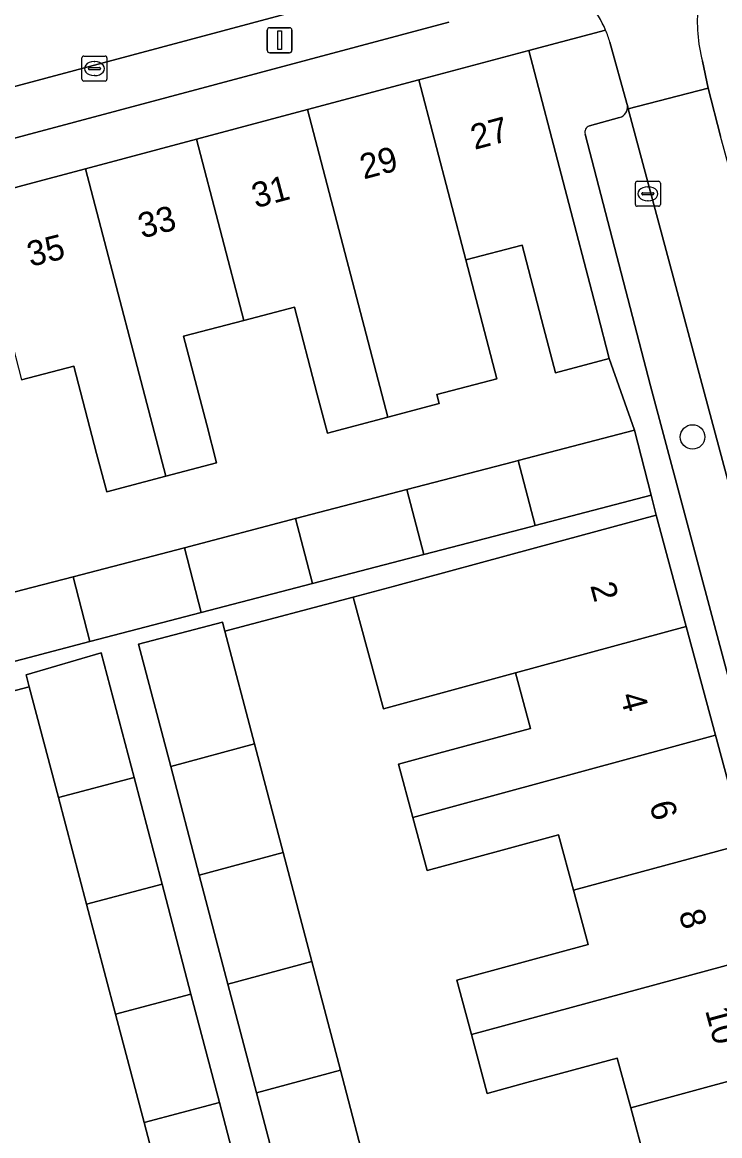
# Model space of a CAD drawing. Extents: x 162542 to 163147, y 380779 to 381521.
# Drawn here: x 162999.98 to 163027.86, y 381074.17 to 381118.69 of the extents above; entities that cross this region are included whole.
import ezdxf

# ---------------------------------------------------------------- set-up
doc = ezdxf.new("R2010")
doc.units = 0
for name, color, linetype in [('IMGEO_Boom', 7, 'Continuous'), ('IMGEO_Erf', 7, 'Continuous'), ('IMGEO_Kolk', 7, 'Continuous'), ('IMGEO_Lichtmast', 7, 'Continuous'), ('IMGEO_Muur', 7, 'Continuous'), ('IMGEO_Pand', 7, 'Continuous'), ('IMGEO_Pand_nummerreeks', 7, 'Continuous'), ('IMGEO_Parkeervlak_open', 7, 'Continuous'), ('IMGEO_Rijbaan_lokaal_open', 7, 'Continuous'), ('IMGEO_Voetpad_open', 7, 'Continuous')]:
    doc.layers.add(name, color=color, linetype=linetype)

msp = doc.modelspace()

# ---------------------------------------------------------------- linework, layer by layer
at = {"layer": 'IMGEO_Boom'}
msp.add_circle((163026.776, 381102.113), 0.489, dxfattribs=at)
at = {"layer": 'IMGEO_Erf'}
for points in [[(162997.557, 381095.362), (163000, 381096), (163002.005, 381096.523), (163006.456, 381097.685), (163010.904, 381098.845), (163015.354, 381100.007), (163019.613, 381101.118), (163019.804, 381101.168), (163024.451, 381102.38), (163023.444, 381105.243), (163021.293, 381104.681), (163020.819, 381106.496), (163019.962, 381109.779), (163017.709, 381109.191), (163018.95, 381104.439), (163016.548, 381103.812), (163016.644, 381103.445), (163014.598, 381102.901), (163012.174, 381102.257), (163011.754, 381103.865), (163010.857, 381107.3), (163008.835, 381106.772), (163006.424, 381106.143), (163007.349, 381102.598), (163007.745, 381101.079), (163005.711, 381100.538), (163003.351, 381099.911), (163002.95, 381101.449), (163002.039, 381104.94), (162999.951, 381104.395)], [(163024.887, 381073.152), (163024.307, 381075.287), (163023.765, 381077.281), (163020.157, 381076.301), (163018.568, 381075.869), (163017.934, 381078.218), (163017.348, 381080.39), (163018.93, 381080.82), (163022.606, 381081.819), (163022.017, 381083.987), (163021.414, 381086.203), (163017.787, 381085.217), (163016.163, 381084.776), (163015.589, 381086.903), (163015.016, 381089.024), (163016.633, 381089.464), (163020.296, 381090.46), (163019.694, 381092.678), (163014.417, 381091.246), (163013.213, 381095.702), (163008.079, 381094.353), (163009.264, 381089.846), (163010.407, 381085.496), (163011.551, 381081.145), (163012.694, 381076.795), (163013.837, 381072.445)], [(163005.987, 381070.367), (163004.846, 381074.7), (163003.704, 381079.036), (163002.549, 381083.426), (163001.425, 381087.692), (163000.258, 381092.125), (162993.238, 381090.278), (162993.844, 381087.979), (162991.901, 381087.466), (162988.211, 381086.491), (162988.779, 381084.344), (162992.497, 381085.326), (162993.101, 381083.041), (162995.014, 381083.547), (162996.389, 381083.91), (162996.918, 381081.91), (162997.485, 381079.764), (162994.218, 381078.9), (162994.806, 381076.675), (162992.491, 381076.063), (162993.072, 381073.867), (162996.808, 381074.855), (162998.633, 381075.337), (162999.186, 381073.201)]]:
    msp.add_lwpolyline(points, dxfattribs=at)
at = {"layer": 'IMGEO_Kolk'}
for p, q in [((163002.362, 381116.413), (163002.362, 381117.265)), ((163002.437, 381117.339), (163003.289, 381117.339)), ((163002.85, 381117.119), (163002.875, 381117.119)), ((163003.363, 381117.265), (163003.363, 381116.413)), ((163002.621, 381116.833), (163002.621, 381116.845)), ((163003.059, 381116.796), (163002.661, 381116.796)), ((163002.664, 381116.882), (163003.062, 381116.882)), ((163002.873, 381116.559), (163002.848, 381116.559)), ((163003.105, 381116.845), (163003.105, 381116.833)), ((163003.289, 381116.339), (163002.437, 381116.339)), ((163024.492, 381111.407), (163024.492, 381112.259)), ((163024.567, 381112.333), (163025.419, 381112.333)), ((163024.98, 381112.113), (163025.005, 381112.113)), ((163025.493, 381112.259), (163025.493, 381111.407)), ((163024.751, 381111.827), (163024.751, 381111.839)), ((163025.189, 381111.79), (163024.791, 381111.79)), ((163024.794, 381111.876), (163025.192, 381111.876)), ((163025.235, 381111.839), (163025.235, 381111.827)), ((163025.419, 381111.333), (163024.567, 381111.333)), ((163025.003, 381111.553), (163024.978, 381111.553))]:
    msp.add_line(p, q, dxfattribs=at)
for points in [[(163002.362, 381116.413), (163002.362, 381117.265)], [(163002.437, 381117.339), (163003.289, 381117.339)], [(163003.363, 381117.265), (163003.363, 381116.413)], [(163003.289, 381116.339), (163002.437, 381116.339)], [(163024.492, 381111.407), (163024.492, 381112.259)], [(163024.567, 381112.333), (163025.419, 381112.333)], [(163025.493, 381112.259), (163025.493, 381111.407)], [(163025.419, 381111.333), (163024.567, 381111.333)]]:
    msp.add_lwpolyline(points, dxfattribs=at)
for centre, radius, start, end in [((163002.439, 381117.263), 0.0765, 91.552, 178.448), ((163002.439, 381117.263), 0.0765, 91.552, 178.448), ((163003.287, 381117.263), 0.0765, 1.552, 88.448), ((163003.287, 381117.263), 0.0765, 1.552, 88.448), ((163002.661, 381116.842), 0.0403, 85.8775, 175.7526), ((163002.658, 381116.832), 0.0366, 178.938, 274.7102), ((163003.062, 381116.839), 0.043, 264.8664, 352.4533), ((163003.066, 381116.844), 0.0386, 1.7309, 96.639), ((163002.439, 381116.415), 0.0765, 181.552, 268.448), ((163002.439, 381116.415), 0.0765, 181.552, 268.448), ((163003.287, 381116.415), 0.0765, 271.552, 358.448), ((163003.287, 381116.415), 0.0765, 271.552, 358.448), ((163024.569, 381112.257), 0.0765, 91.552, 178.448), ((163024.569, 381112.257), 0.0765, 91.552, 178.448), ((163025.417, 381112.257), 0.0765, 1.552, 88.448), ((163025.417, 381112.257), 0.0765, 1.552, 88.448), ((163024.791, 381111.836), 0.0403, 85.8775, 175.7526), ((163024.788, 381111.826), 0.0366, 178.938, 274.7102), ((163025.192, 381111.833), 0.043, 264.8664, 352.4533), ((163025.196, 381111.838), 0.0386, 1.7309, 96.639), ((163024.569, 381111.409), 0.0765, 181.552, 268.448), ((163024.569, 381111.409), 0.0765, 181.552, 268.448), ((163025.417, 381111.409), 0.0765, 271.552, 358.448), ((163025.417, 381111.409), 0.0765, 271.552, 358.448)]:
    msp.add_arc(centre, radius, start, end, dxfattribs=at)
for centre, major_axis, ratio, start_param, end_param in [((163002.849, 381116.839), (-0.387, 0.002), 0.722429, 4.712389, 7.853982), ((163002.874, 381116.839), (-0.39, 0.002), 0.717154, 1.570796, 4.712389), ((163024.979, 381111.833), (-0.387, 0.002), 0.722429, 4.712389, 7.853982), ((163025.004, 381111.833), (-0.39, 0.002), 0.717154, 1.570796, 4.712389)]:
    msp.add_ellipse(centre, major_axis=major_axis, ratio=ratio, start_param=start_param, end_param=end_param, dxfattribs=at)
at = {"layer": 'IMGEO_Lichtmast'}
for p, q in [((163009.77, 381117.571), (163009.77, 381118.371)), ((163009.77, 381118.371), (163009.77, 381117.571)), ((163009.87, 381118.471), (163010.66, 381118.471)), ((163010.66, 381118.471), (163009.87, 381118.471)), ((163010.76, 381118.371), (163010.76, 381117.571)), ((163010.76, 381117.571), (163010.76, 381118.371)), ((163010.66, 381117.471), (163009.87, 381117.471)), ((163009.87, 381117.471), (163010.66, 381117.471))]:
    msp.add_line(p, q, dxfattribs=at)
msp.add_lwpolyline([(163010.19, 381118.346), (163010.34, 381118.346), (163010.34, 381117.596), (163010.19, 381117.596), (163010.19, 381118.346)], dxfattribs=at)
for centre, start, end in [((163009.87, 381118.371), 90, 180), ((163009.87, 381118.371), 90, 180), ((163010.66, 381118.371), 0, 90), ((163010.66, 381118.371), 360, 90), ((163009.87, 381117.571), 180, 270), ((163009.87, 381117.571), 180, 270), ((163010.66, 381117.571), 270, 0), ((163010.66, 381117.571), 270, 0)]:
    msp.add_arc(centre, 0.1, start, end, dxfattribs=at)
at = {"layer": 'IMGEO_Muur'}
msp.add_lwpolyline([(163023.444, 381105.243), (163024.451, 381102.38)], dxfattribs=at)
at = {"layer": 'IMGEO_Pand'}
for points in [[(163017.709, 381109.191), (163019.962, 381109.779), (163020.819, 381106.496), (163021.293, 381104.681), (163023.444, 381105.243), (163022.97, 381107.057), (163020.229, 381117.56), (163015.83, 381116.387)], [(163011.387, 381115.201), (163014.598, 381102.901), (163016.644, 381103.445), (163016.548, 381103.812), (163018.95, 381104.439), (163017.709, 381109.191), (163015.83, 381116.387)], [(163006.944, 381114.016), (163008.835, 381106.772), (163010.857, 381107.3), (163011.754, 381103.865), (163012.174, 381102.257), (163014.598, 381102.901), (163011.387, 381115.201)], [(163005.711, 381100.538), (163007.745, 381101.079), (163007.349, 381102.598), (163006.424, 381106.143), (163008.835, 381106.772), (163006.944, 381114.016), (163002.501, 381112.831)], [(163005.711, 381100.538), (163002.501, 381112.831), (163000, 381112.164), (162998.059, 381111.646), (162999.951, 381104.395), (163002.039, 381104.94), (163002.95, 381101.449), (163003.351, 381099.911)], [(163020.481, 381098.574), (163025.128, 381099.786), (163024.451, 381102.38), (163019.804, 381101.168)], [(163020.481, 381098.574), (163019.804, 381101.168), (163019.613, 381101.118), (163015.354, 381100.007), (163016.031, 381097.412), (163020.291, 381098.524)], [(163011.581, 381096.251), (163016.031, 381097.412), (163015.354, 381100.007), (163010.904, 381098.845)], [(163006.456, 381097.685), (163007.133, 381095.091), (163011.581, 381096.251), (163010.904, 381098.845)], [(163026.522, 381094.532), (163025.317, 381098.99), (163020.492, 381097.679), (163014.81, 381096.136), (163013.213, 381095.702), (163014.417, 381091.246), (163019.694, 381092.678)], [(163002.005, 381096.523), (163002.682, 381093.929), (163007.133, 381095.091), (163006.456, 381097.685)], [(163002.005, 381096.523), (163000, 381096), (162997.557, 381095.362), (162998.235, 381092.768), (163000, 381093.229), (163002.682, 381093.929)], [(163008.079, 381094.353), (163007.986, 381094.708), (163004.625, 381093.826), (163005.911, 381088.935), (163009.264, 381089.846)], [(163026.522, 381094.532), (163019.694, 381092.678), (163020.296, 381090.46), (163016.633, 381089.464), (163015.016, 381089.024), (163015.589, 381086.903), (163027.696, 381090.19)], [(163003.134, 381093.483), (163000.134, 381092.598), (163000.258, 381092.125), (163001.425, 381087.692), (163004.446, 381088.492)], [(163010.407, 381085.496), (163009.264, 381089.846), (163005.911, 381088.935), (163007.054, 381084.586)], [(163027.696, 381090.19), (163015.589, 381086.903), (163016.163, 381084.776), (163017.787, 381085.217), (163021.414, 381086.203), (163022.017, 381083.987), (163028.87, 381085.848)], [(163001.425, 381087.692), (163002.549, 381083.426), (163005.564, 381084.235), (163004.446, 381088.492)], [(163017.934, 381078.218), (163030.044, 381081.506), (163028.87, 381085.848), (163022.017, 381083.987), (163022.606, 381081.819), (163018.93, 381080.82), (163017.348, 381080.39)], [(163010.407, 381085.496), (163007.054, 381084.586), (163008.197, 381080.234), (163011.551, 381081.145)], [(163005.564, 381084.235), (163002.549, 381083.426), (163003.704, 381079.036), (163006.721, 381079.835)], [(163017.934, 381078.218), (163018.568, 381075.869), (163020.157, 381076.301), (163023.765, 381077.281), (163024.307, 381075.287), (163031.218, 381077.163), (163030.044, 381081.506)], [(163009.34, 381075.885), (163012.694, 381076.795), (163011.551, 381081.145), (163008.197, 381080.234)], [(163004.846, 381074.7), (163007.86, 381075.498), (163006.721, 381079.835), (163003.704, 381079.036)], [(163031.218, 381077.163), (163024.307, 381075.287), (163024.887, 381073.152), (163021.3, 381072.178), (163019.683, 381071.739), (163019.329, 381071.643), (163019.925, 381069.436), (163032.392, 381072.821)], [(163009.34, 381075.885), (163010.483, 381071.535), (163013.837, 381072.445), (163012.694, 381076.795)], [(163004.846, 381074.7), (163005.987, 381070.367), (163008.999, 381071.164), (163007.86, 381075.498)]]:
    msp.add_lwpolyline(points, close=True, dxfattribs=at)
at = {"layer": 'IMGEO_Parkeervlak_open'}
for points in [[(163017.219, 381120.83), (163017.107, 381120.8), (163016.022, 381120.51), (162980.068, 381110.891)], [(162981.246, 381109.144), (163017.038, 381118.691)], [(163028.907, 381097.696), (163024.207, 381115.224), (163024.17, 381115.363)], [(163023.86, 381114.888), (163022.656, 381114.552)], [(163022.488, 381114.212), (163025.098, 381104.154), (163040.537, 381046.316), (163041.163, 381044.025)]]:
    msp.add_lwpolyline(points, dxfattribs=at)
for centre, radius, start, end in [((163023.759, 381115.292), 0.417, 284, 9.7406), ((163022.742, 381114.298), 0.268, 108.711, 198.6994)]:
    msp.add_arc(centre, radius, start, end, dxfattribs=at)
at = {"layer": 'IMGEO_Rijbaan_lokaal_open'}
for points in [[(163017.107, 381120.8), (163016.087, 381124.68), (162980.601, 381115.195), (162980.082, 381115.076), (162975.55, 381113.864), (162976.575, 381109.968), (162980.068, 381110.891), (163016.022, 381120.51)], [(163027.891, 381114.14), (163027.397, 381116.055), (163024.207, 381115.224), (163028.907, 381097.696), (163034.368, 381077.25), (163037.584, 381078.128), (163030.851, 381103.35)]]:
    msp.add_lwpolyline(points, close=True, dxfattribs=at)
msp.add_lwpolyline([(163023.47, 381117.898), (163024.15, 381115.438), (163024.17, 381115.363), (163024.207, 381115.224), (163027.397, 381116.055), (163027.173, 381117.133)], dxfattribs=at)
for centre, radius, start, end in [((163019.41, 381116.732), 4.224, 22.9321, 56.5349), ((163033.071, 381118.715), 6.106, 173.9148, 195.0124), ((163019.184, 381116.65), 4.464, 16.2331, 22.7718)]:
    msp.add_arc(centre, radius, start, end, dxfattribs=at)
at = {"layer": 'IMGEO_Voetpad_open'}
for points in [[(163017.038, 381118.691), (162981.246, 381109.144)], [(163000, 381112.164), (163002.501, 381112.831), (163006.944, 381114.016), (163011.387, 381115.201), (163015.83, 381116.387), (163020.229, 381117.56), (163023.3, 381118.378)], [(163023.3, 381118.378), (163020.229, 381117.56), (163022.97, 381107.057), (163023.444, 381105.243), (163024.451, 381102.38), (163025.128, 381099.786), (163025.317, 381098.99), (163026.522, 381094.532), (163027.696, 381090.19), (163028.87, 381085.848), (163030.044, 381081.506), (163031.218, 381077.163), (163032.392, 381072.821), (163033.566, 381068.479), (163034.74, 381064.136), (163035.913, 381059.794), (163037.087, 381055.452), (163037.197, 381055.046), (163038.277, 381051.052), (163039.466, 381046.653), (163039.624, 381046.069)], [(163024.17, 381115.363), (163024.15, 381115.438), (163023.47, 381117.898)], [(163027.173, 381117.133), (163027.397, 381116.055), (163027.891, 381114.14)], [(163022.656, 381114.552), (163023.86, 381114.888)], [(163041.163, 381044.025), (163040.537, 381046.316), (163025.098, 381104.154), (163022.488, 381114.212)], [(162972.544, 381104.918), (162975.624, 381105.661), (162980.286, 381106.905), (162984.729, 381108.09), (162989.172, 381109.275), (162993.615, 381110.461), (162998.059, 381111.646), (163000, 381112.164)], [(163010.483, 381071.535), (163009.34, 381075.885), (163008.197, 381080.234), (163007.054, 381084.586), (163005.911, 381088.935), (163004.625, 381093.826), (163007.986, 381094.708), (163008.079, 381094.353), (163013.213, 381095.702), (163014.81, 381096.136), (163020.492, 381097.679), (163025.317, 381098.99), (163025.128, 381099.786), (163020.481, 381098.574), (163020.291, 381098.524), (163016.031, 381097.412), (163011.581, 381096.251), (163007.133, 381095.091), (163002.682, 381093.929), (163000, 381093.229), (162998.235, 381092.768)], [(162993.238, 381090.278), (163000.258, 381092.125), (163000.134, 381092.598), (163003.134, 381093.483), (163004.446, 381088.492), (163005.564, 381084.235), (163006.721, 381079.835), (163007.86, 381075.498), (163008.999, 381071.164)]]:
    msp.add_lwpolyline(points, dxfattribs=at)
for centre, radius, start, end in [((163019.41, 381116.732), 4.224, 22.9321, 56.5349), ((163033.071, 381118.715), 6.106, 173.9148, 195.0124), ((163019.184, 381116.65), 4.464, 16.2331, 22.7718), ((163023.759, 381115.292), 0.417, 284, 9.7406), ((163022.742, 381114.298), 0.268, 108.711, 198.6994)]:
    msp.add_arc(centre, radius, start, end, dxfattribs=at)

# ---------------------------------------------------------------- texts
at = {"layer": 'IMGEO_Pand_nummerreeks'}
for s, rotation, p in [('27', 14.9356, (163018.059, 381113.587)), ('29', 14.937, (163013.628, 381112.404)), ('31', 14.9356, (163009.306, 381111.251)), ('33', 14.9356, (163004.764, 381110.04)), ('35', 13.8925, (163000.307, 381108.91)), ('2', 285.1136, (163022.68, 381096.174)), ('4', 285.1423, (163023.87, 381091.769)), ('6', 285.1287, (163025.044, 381087.429)), ('8', 285.1281, (163026.219, 381083.083)), ('10', 285.1281, (163027.274, 381079.186))]:
    msp.add_text(s, height=1, rotation=rotation, dxfattribs=at).set_placement(p)

doc.saveas('drawing.dxf')
